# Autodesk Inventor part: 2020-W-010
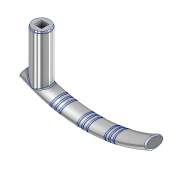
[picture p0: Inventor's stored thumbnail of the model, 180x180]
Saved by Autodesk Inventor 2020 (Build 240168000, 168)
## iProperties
Created: 2016-07
Part Number: 2020-W-010
Material: Aluminium 6061
Document SubType Name: Modeling
Designer: F.Stasiak
Density: 2.7 g/cm^3
Appearance: Aluminium — płaski
Manager: www.cadconsulting.pl
Company: Fabian Stasiak CAD Consulting
Author: F.Stasiak
Subject: Zbiór ćwiczeń. Autodesk Inventor 2020. Kurs podstawowy
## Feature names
1. Przeciągnięcie1
2. Wyciągnięcie proste1 [Extrusion]
3. Wyciągnięcie proste2 [Extrusion]
4. Zaokrąglenie1 [Fillet]
5. Szyk prostokątny1 [Rectangular Pattern]
6. Szyk prostokątny2 [Rectangular Pattern]
7. Wyciągnięcie proste3 [Extrusion]
8. Wyciągnięcie proste4 [Extrusion]
9. Zaokrąglenie2 [Fillet]
## Parameters: d3 = 15 mm, d5 = 5.5 mm, d6 = 0, d7 = 0, d10 = 0, d11 = 0.5 mm, d12 = 1 mm, d13 = 1.5 mm, d14 = 0, d15 = 1.5 mm, d18 = 5 mm, d22 = 8 mm, d23 = 8 mm, d24 = 15 mm, d25 = 0, d26 = 0.75 mm, d27 = 2 mm, d28 = 0, d29 = 1.5 mm
